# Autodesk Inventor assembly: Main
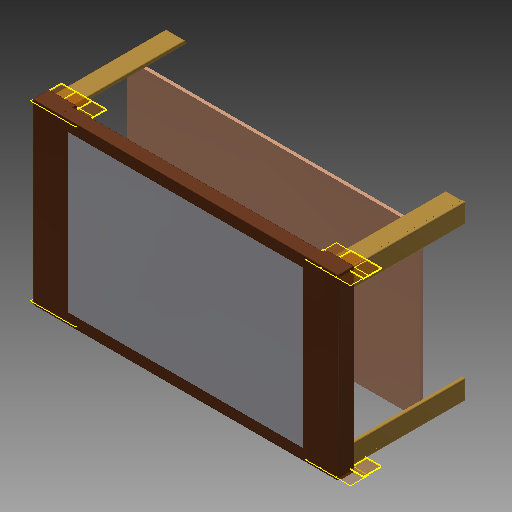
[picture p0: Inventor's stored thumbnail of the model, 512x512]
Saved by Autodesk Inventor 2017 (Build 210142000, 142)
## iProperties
Created: 2017-05
Part Number: Main
Document SubType Name: Assembly
Designer: Savy
Sending System: SIEMENS PLM Software NX 10.0
Preprocessor: ST-DEVELOPER v16
Title: Main_stp_stp.stp
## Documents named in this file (4)
- D:\3D Printer Designs\John Ledden Designs\Infinity Mirror Table\SavanDrawings\Main.iam
- D:\3D Printer Designs\John Ledden Designs\Infinity Mirror Table\SavanDrawings\Top.iam
- D:\3D Printer Designs\John Ledden Designs\Infinity Mirror Table\SavanDrawings\Bottom.iam
- D:\3D Printer Designs\John Ledden Designs\Infinity Mirror Table\SavanDrawings\Legs.iam
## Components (3 placed, 3 different names)
1. Top_1339 [sub-assembly]
2. Bottom_1340 [sub-assembly]
3. Legs_1341 [sub-assembly]
